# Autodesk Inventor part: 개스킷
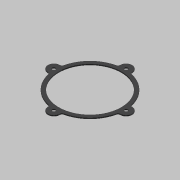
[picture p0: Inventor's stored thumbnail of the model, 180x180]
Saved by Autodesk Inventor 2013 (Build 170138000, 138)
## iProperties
Created: 2018-05
Part Number: 개스킷
Material: 고무, 실리콘
Document SubType Name: Modeling
Designer: mduedu
Density: 1.25 g/cm^3
Mass: 3.74063 g
Surface Area: 50.7921 cm^2
Volume: 2.99251 cm^3
Author: mduedu
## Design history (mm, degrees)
sketch "스케치1"
  geometry: C1 r 45 at (0, 0); C2 r 50 at (0, 0); 1 further point
  constraints: 2 centre point, 1 coincident, 1 concentric
  dimensions: "d12" = 90 diameter of C1; "d14" = 100 diameter of C2
extrude "돌출1" new body sketch "스케치1" distance "d10" = 1.5; taper "d11" = 0 deg
sketch "스케치2"
  geometry: C1 r 50 at (0, 0) reference; A1 r 8.5 centre (0, 52) between (8.074, 49.344) and (-8.074, 49.344); A2 r 50 centre (0, 0) between (-8.074, 49.344) and (8.074, 49.344); A3 r 8.5 centre (0, 52) between (-8.074, 49.344) and (8.074, 49.344); 1 further point
  constraints: 6 point on circle, 3 centre point, 1 concentric, 1 vertical alignment
  dimensions: "d15" = 52 distance of A1.centre point (0, 0); "d16" = 8.5 radius of A1; "d17" = 100 diameter of A2
extrude "돌출2" join sketch "스케치2" stored distance "d18" = 10; taper "d19" = 0 deg
sketch "스케치3"
  geometry: C1 r 2.5 at (0, 52); A1 r 8.5 centre (0, 52) between (8.074, 49.344) and (-8.074, 49.344) reference; 1 further point
  constraints: 1 centre point, 1 concentric
  dimensions: "d20" = 5 diameter of C1
extrude "돌출3" cut sketch "스케치3" stored distance "d21" = 10; taper "d22" = 0 deg
fillet "모깎기1" dims "d23" = 3
node "솔리드1"
pattern_circular "원형 패턴1" dims "d25" = 360 deg
